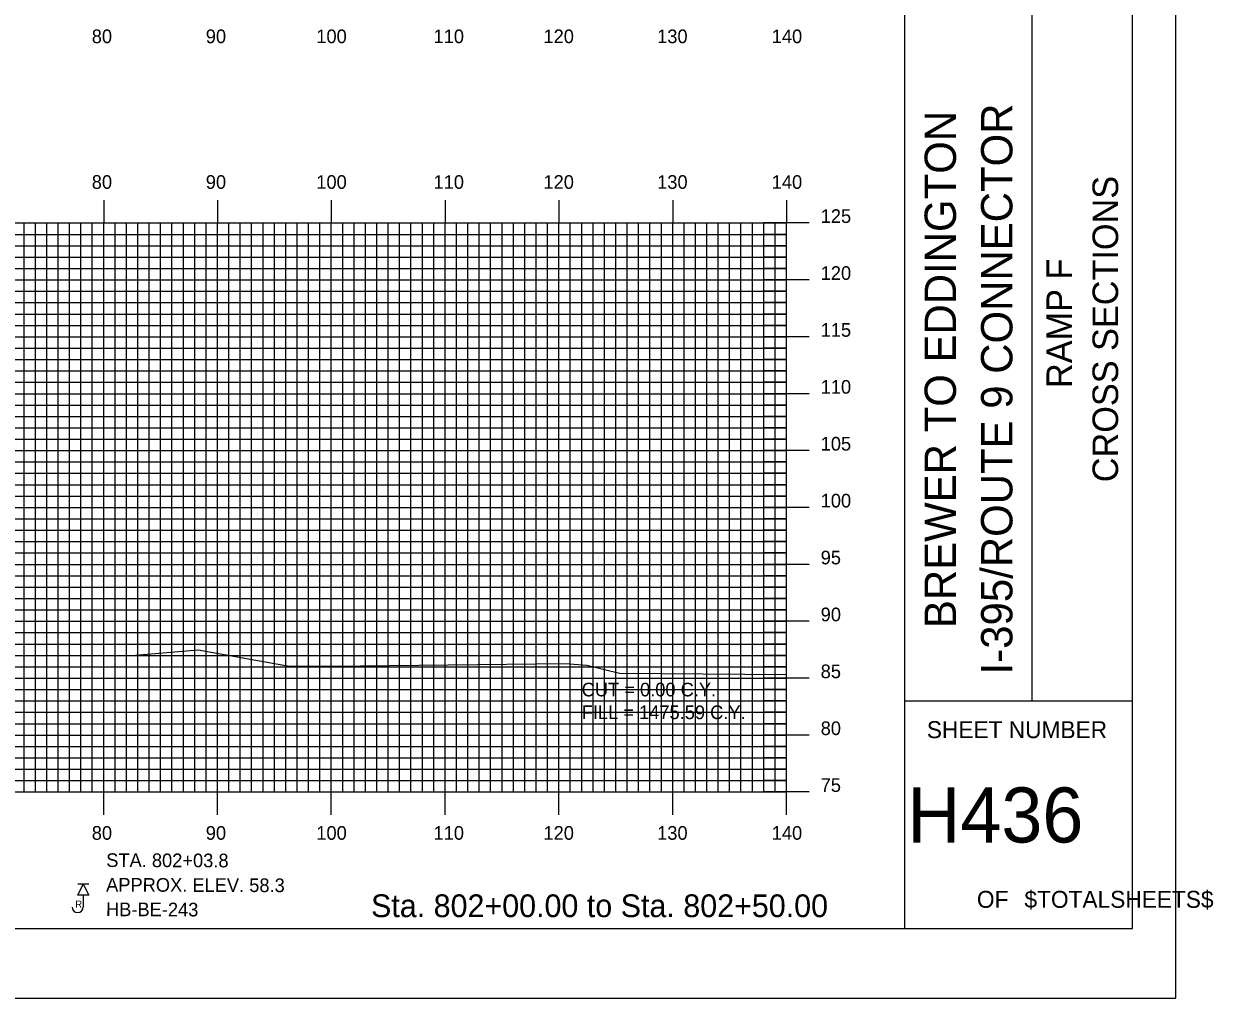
# Model space of a CAD drawing. Extents: x -302 to 42, y -1658 to -1438.
# Drawn here: x -62.9 to 41.6, y -1657.7 to -1572.1 of the extents above; entities that cross this region are included whole.
import ezdxf

# ---------------------------------------------------------------- set-up
doc = ezdxf.new("R2010")
doc.units = 0
for name, color, linetype in [('BORDER', 7, 'Continuous'), ('BORING - REFUSAL', 7, 'Continuous'), ('D_Text_Standard', 7, 'Continuous'), ('H_V ANNOTATION', 7, 'Continuous'), ('MAJOR', 7, 'Continuous'), ('MINOR', 7, 'Continuous'), ('PLOT BOUNDARY', 7, 'Continuous'), ('S_Roadway_Centerline', 7, 'Continuous')]:
    doc.layers.add(name, color=color, linetype=linetype)

msp = doc.modelspace()

# ---------------------------------------------------------------- linework, layer by layer
at = {"layer": 'BORDER'}
for p, q in [((14.51, -1651.6), (14.51, -1441.6)), ((25.69, -1631.6), (25.69, -1561.6)), ((14.51, -1631.6), (34.51, -1631.6))]:
    msp.add_line(p, q, dxfattribs=at)
msp.add_lwpolyline([(-285.49, -1651.6), (34.51, -1651.6), (34.51, -1441.6), (-285.49, -1441.6)], close=True, dxfattribs=at)
at = {"layer": 'BORING - REFUSAL'}
for p, q in [((-57.21, -1647.7), (-58.17, -1647.7)), ((-57.69, -1648.66), (-57.69, -1649.72))]:
    msp.add_line(p, q, dxfattribs=at)
msp.add_lwpolyline([(-57.69, -1647.7), (-57.21, -1648.66), (-58.17, -1648.66)], close=True, dxfattribs=at)
msp.add_arc((-58.18, -1649.72), 0.485, 180, 0, dxfattribs=at)
at = {"layer": 'MAJOR'}
for p, q in [((-55.89, -1587.6), (-55.89, -1589.6)), ((-45.89, -1587.6), (-45.89, -1589.6)), ((-35.89, -1587.6), (-35.89, -1589.6)), ((-25.89, -1587.6), (-25.89, -1589.6)), ((-15.89, -1587.6), (-15.89, -1589.6)), ((-5.89, -1587.6), (-5.89, -1589.6)), ((4.11, -1587.6), (4.11, -1589.6)), ((-275.89, -1589.6), (4.11, -1589.6)), ((-275.89, -1589.6), (4.11, -1589.6)), ((-55.89, -1639.6), (-55.89, -1589.6)), ((-45.89, -1639.6), (-45.89, -1589.6)), ((-35.89, -1639.6), (-35.89, -1589.6)), ((-25.89, -1639.6), (-25.89, -1589.6)), ((-15.89, -1639.6), (-15.89, -1589.6)), ((-5.89, -1639.6), (-5.89, -1589.6)), ((6.11, -1589.6), (2.1, -1589.6)), ((4.11, -1639.6), (4.11, -1589.6)), ((4.11, -1639.6), (4.11, -1589.6)), ((-275.89, -1594.6), (4.11, -1594.6)), ((6.11, -1594.6), (2.1, -1594.6)), ((-275.89, -1599.6), (4.11, -1599.6)), ((6.11, -1599.6), (2.1, -1599.6)), ((-275.89, -1604.6), (4.11, -1604.6)), ((6.11, -1604.6), (2.1, -1604.6)), ((-275.89, -1609.6), (4.11, -1609.6)), ((6.11, -1609.6), (2.1, -1609.6)), ((-275.89, -1614.6), (4.11, -1614.6)), ((6.11, -1614.6), (2.1, -1614.6)), ((-275.89, -1619.6), (4.11, -1619.6)), ((6.11, -1619.6), (2.1, -1619.6)), ((-275.89, -1624.6), (4.11, -1624.6)), ((6.11, -1624.6), (2.1, -1624.6)), ((-275.89, -1629.6), (4.11, -1629.6)), ((6.11, -1629.6), (2.1, -1629.6)), ((-275.89, -1634.6), (4.11, -1634.6)), ((6.11, -1634.6), (2.1, -1634.6)), ((-275.89, -1639.6), (4.11, -1639.6)), ((-275.89, -1639.6), (4.11, -1639.6)), ((-55.89, -1641.61), (-55.89, -1639.6)), ((-45.89, -1641.61), (-45.89, -1639.6)), ((-35.89, -1641.61), (-35.89, -1639.6)), ((-25.89, -1641.61), (-25.89, -1639.6)), ((-15.89, -1641.61), (-15.89, -1639.6)), ((-5.89, -1641.61), (-5.89, -1639.6)), ((6.11, -1639.6), (2.1, -1639.6)), ((4.11, -1641.61), (4.11, -1639.6))]:
    msp.add_line(p, q, dxfattribs=at)
at = {"layer": 'MINOR'}
for p, q in [((-62.89, -1639.6), (-62.89, -1589.6)), ((-61.89, -1639.6), (-61.89, -1589.6)), ((-60.89, -1639.6), (-60.89, -1589.6)), ((-59.89, -1639.6), (-59.89, -1589.6)), ((-58.89, -1639.6), (-58.89, -1589.6)), ((-57.89, -1639.6), (-57.89, -1589.6)), ((-56.89, -1639.6), (-56.89, -1589.6)), ((-54.89, -1639.6), (-54.89, -1589.6)), ((-53.89, -1639.6), (-53.89, -1589.6)), ((-52.89, -1639.6), (-52.89, -1589.6)), ((-51.89, -1639.6), (-51.89, -1589.6)), ((-50.89, -1639.6), (-50.89, -1589.6)), ((-49.89, -1639.6), (-49.89, -1589.6)), ((-48.89, -1639.6), (-48.89, -1589.6)), ((-47.89, -1639.6), (-47.89, -1589.6)), ((-46.89, -1639.6), (-46.89, -1589.6)), ((-44.89, -1639.6), (-44.89, -1589.6)), ((-43.89, -1639.6), (-43.89, -1589.6)), ((-42.89, -1639.6), (-42.89, -1589.6)), ((-41.89, -1639.6), (-41.89, -1589.6)), ((-40.89, -1639.6), (-40.89, -1589.6)), ((-39.89, -1639.6), (-39.89, -1589.6)), ((-38.89, -1639.6), (-38.89, -1589.6)), ((-37.89, -1639.6), (-37.89, -1589.6)), ((-36.89, -1639.6), (-36.89, -1589.6)), ((-34.89, -1639.6), (-34.89, -1589.6)), ((-33.89, -1639.6), (-33.89, -1589.6)), ((-32.89, -1639.6), (-32.89, -1589.6)), ((-31.89, -1639.6), (-31.89, -1589.6)), ((-30.89, -1639.6), (-30.89, -1589.6)), ((-29.89, -1639.6), (-29.89, -1589.6)), ((-28.89, -1639.6), (-28.89, -1589.6)), ((-27.89, -1639.6), (-27.89, -1589.6)), ((-26.89, -1639.6), (-26.89, -1589.6)), ((-24.89, -1639.6), (-24.89, -1589.6)), ((-23.89, -1639.6), (-23.89, -1589.6)), ((-22.89, -1639.6), (-22.89, -1589.6)), ((-21.89, -1639.6), (-21.89, -1589.6)), ((-20.89, -1639.6), (-20.89, -1589.6)), ((-19.89, -1639.6), (-19.89, -1589.6)), ((-18.89, -1639.6), (-18.89, -1589.6)), ((-17.89, -1639.6), (-17.89, -1589.6)), ((-16.89, -1639.6), (-16.89, -1589.6)), ((-14.89, -1639.6), (-14.89, -1589.6)), ((-13.89, -1639.6), (-13.89, -1589.6)), ((-12.89, -1639.6), (-12.89, -1589.6)), ((-11.89, -1639.6), (-11.89, -1589.6)), ((-10.89, -1639.6), (-10.89, -1589.6)), ((-9.89, -1639.6), (-9.89, -1589.6)), ((-8.89, -1639.6), (-8.89, -1589.6)), ((-7.89, -1639.6), (-7.89, -1589.6)), ((-6.89, -1639.6), (-6.89, -1589.6)), ((-4.89, -1639.6), (-4.89, -1589.6)), ((-3.89, -1639.6), (-3.89, -1589.6)), ((-2.89, -1639.6), (-2.89, -1589.6)), ((-1.89, -1639.6), (-1.89, -1589.6)), ((-0.89, -1639.6), (-0.89, -1589.6)), ((0.11, -1639.6), (0.11, -1589.6)), ((1.11, -1639.6), (1.11, -1589.6)), ((2.11, -1639.6), (2.11, -1589.6)), ((3.11, -1639.6), (3.11, -1589.6)), ((-275.89, -1590.6), (4.11, -1590.6)), ((4.11, -1590.6), (2.1, -1590.6)), ((-275.89, -1591.6), (4.11, -1591.6)), ((4.11, -1591.6), (2.1, -1591.6)), ((-275.89, -1592.6), (4.11, -1592.6)), ((4.11, -1592.6), (2.1, -1592.6)), ((-275.89, -1593.6), (4.11, -1593.6)), ((4.11, -1593.6), (2.1, -1593.6)), ((-275.89, -1595.6), (4.11, -1595.6)), ((4.11, -1595.6), (2.1, -1595.6)), ((-275.89, -1596.6), (4.11, -1596.6)), ((4.11, -1596.6), (2.1, -1596.6)), ((-275.89, -1597.6), (4.11, -1597.6)), ((4.11, -1597.6), (2.1, -1597.6)), ((-275.89, -1598.6), (4.11, -1598.6)), ((4.11, -1598.6), (2.1, -1598.6)), ((-275.89, -1600.6), (4.11, -1600.6)), ((4.11, -1600.6), (2.1, -1600.6)), ((-275.89, -1601.6), (4.11, -1601.6)), ((4.11, -1601.6), (2.1, -1601.6)), ((-275.89, -1602.6), (4.11, -1602.6)), ((4.11, -1602.6), (2.1, -1602.6)), ((-275.89, -1603.6), (4.11, -1603.6)), ((4.11, -1603.6), (2.1, -1603.6)), ((-275.89, -1605.6), (4.11, -1605.6)), ((4.11, -1605.6), (2.1, -1605.6)), ((-275.89, -1606.6), (4.11, -1606.6)), ((4.11, -1606.6), (2.1, -1606.6)), ((-275.89, -1607.6), (4.11, -1607.6)), ((4.11, -1607.6), (2.1, -1607.6)), ((-275.89, -1608.6), (4.11, -1608.6)), ((4.11, -1608.6), (2.1, -1608.6)), ((-275.89, -1610.6), (4.11, -1610.6)), ((4.11, -1610.6), (2.1, -1610.6)), ((-275.89, -1611.6), (4.11, -1611.6)), ((4.11, -1611.6), (2.1, -1611.6)), ((-275.89, -1612.6), (4.11, -1612.6)), ((4.11, -1612.6), (2.1, -1612.6)), ((-275.89, -1613.6), (4.11, -1613.6)), ((4.11, -1613.6), (2.1, -1613.6)), ((-275.89, -1615.6), (4.11, -1615.6)), ((4.11, -1615.6), (2.1, -1615.6)), ((-275.89, -1616.6), (4.11, -1616.6)), ((4.11, -1616.6), (2.1, -1616.6)), ((-275.89, -1617.6), (4.11, -1617.6)), ((4.11, -1617.6), (2.1, -1617.6)), ((-275.89, -1618.6), (4.11, -1618.6)), ((4.11, -1618.6), (2.1, -1618.6)), ((-275.89, -1620.6), (4.11, -1620.6)), ((4.11, -1620.6), (2.1, -1620.6)), ((-275.89, -1621.6), (4.11, -1621.6)), ((4.11, -1621.6), (2.1, -1621.6)), ((-275.89, -1622.6), (4.11, -1622.6)), ((4.11, -1622.6), (2.1, -1622.6)), ((-275.89, -1623.6), (4.11, -1623.6)), ((4.11, -1623.6), (2.1, -1623.6)), ((-275.89, -1625.6), (4.11, -1625.6)), ((4.11, -1625.6), (2.1, -1625.6)), ((-275.89, -1626.6), (4.11, -1626.6)), ((4.11, -1626.6), (2.1, -1626.6)), ((-275.89, -1627.6), (4.11, -1627.6)), ((4.11, -1627.6), (2.1, -1627.6)), ((-275.89, -1628.6), (4.11, -1628.6)), ((4.11, -1628.6), (2.1, -1628.6)), ((-275.89, -1630.6), (4.11, -1630.6)), ((4.11, -1630.6), (2.1, -1630.6)), ((-275.89, -1631.6), (4.11, -1631.6)), ((4.11, -1631.6), (2.1, -1631.6)), ((-275.89, -1632.6), (4.11, -1632.6)), ((4.11, -1632.6), (2.1, -1632.6)), ((-275.89, -1633.6), (4.11, -1633.6)), ((4.11, -1633.6), (2.1, -1633.6)), ((-275.89, -1635.6), (4.11, -1635.6)), ((4.11, -1635.6), (2.1, -1635.6)), ((-275.89, -1636.6), (4.11, -1636.6)), ((4.11, -1636.6), (2.1, -1636.6)), ((-275.89, -1637.6), (4.11, -1637.6)), ((4.11, -1637.6), (2.1, -1637.6)), ((-275.89, -1638.6), (4.11, -1638.6)), ((4.11, -1638.6), (2.1, -1638.6))]:
    msp.add_line(p, q, dxfattribs=at)
at = {"layer": 'PLOT BOUNDARY'}
msp.add_lwpolyline([(-301.68, -1657.72), (38.32, -1657.72), (38.32, -1437.72), (-301.68, -1437.72)], close=True, dxfattribs=at)
at = {"layer": 'S_Roadway_Centerline'}
msp.add_lwpolyline([(-64, -1627.57), (-53.46, -1627.62), (-47.6, -1627.11), (-39.73, -1628.52), (-35.91, -1628.55), (-15.34, -1628.32), (-13.44, -1628.46), (-10.58, -1629.16), (4.11, -1629.29)], dxfattribs=at)

# ---------------------------------------------------------------- texts
at = {"layer": 'BORDER'}
for s, height, p in [('BREWER TO EDDINGTON', 2.7557, (19, -1625.2)), ('I-395/ROUTE 9 CONNECTOR', 2.7557, (23.96, -1629.27)), ('CROSS SECTIONS', 2.25, (33.25, -1612.38)), ('RAMP F', 2.25, (29.2, -1604.1))]:
    msp.add_text(s, height=height, rotation=90, dxfattribs=at).set_placement(p)
for s, height, p in [('SHEET NUMBER', 1.4905, (16.44, -1634.87)), ('H436', 4.839, (14.72, -1644.04)), ('$TOTALSHEETS$', 1.4905, (25.02, -1649.78)), ('OF', 1.491, (20.84, -1649.78))]:
    msp.add_text(s, height=height, dxfattribs=at).set_placement(p)
at = {"layer": 'BORING - REFUSAL'}
for s, p in [('STA. 802+03.8', (-55.67, -1646.19)), ('APPROX. ELEV. 58.3', (-55.68, -1648.35)), ('HB-BE-243', (-55.69, -1650.51))]:
    msp.add_text(s, height=1.2, rotation=359.8142, dxfattribs=at).set_placement(p)
msp.add_text('R', height=0.64, dxfattribs=at).set_placement((-58.4, -1649.78))
at = {"layer": 'D_Text_Standard'}
for s, p in [('CUT = 0.00 C.Y.', (-13.89, -1631.2)), ('FILL = 1475.59 C.Y.', (-13.89, -1633.2))]:
    msp.add_text(s, height=1.2, dxfattribs=at).set_placement(p)
at = {"layer": 'H_V ANNOTATION'}
for s, height, p in [('80', 1.2, (-56.94, -1573.8)), ('90', 1.2, (-46.92, -1573.8)), ('100', 1.2, (-37.21, -1573.8)), ('110', 1.2, (-26.91, -1573.8)), ('120', 1.2, (-17.25, -1573.8)), ('130', 1.2, (-7.26, -1573.8)), ('140', 1.2, (2.81, -1573.8)), ('80', 1.2, (-56.94, -1586.6)), ('90', 1.2, (-46.92, -1586.6)), ('100', 1.2, (-37.21, -1586.6)), ('110', 1.2, (-26.91, -1586.6)), ('120', 1.2, (-17.25, -1586.6)), ('130', 1.2, (-7.26, -1586.6)), ('140', 1.2, (2.81, -1586.6)), ('125', 1.2, (7.11, -1589.6)), ('120', 1.2, (7.11, -1594.6)), ('115', 1.2, (7.11, -1599.6)), ('110', 1.2, (7.11, -1604.6)), ('105', 1.2, (7.11, -1609.6)), ('100', 1.2, (7.11, -1614.6)), ('95', 1.2, (7.11, -1619.6)), ('90', 1.2, (7.11, -1624.6)), ('85', 1.2, (7.11, -1629.6)), ('80', 1.2, (7.11, -1634.6)), ('75', 1.2, (7.11, -1639.6)), ('80', 1.2, (-56.94, -1643.8)), ('90', 1.2, (-46.92, -1643.8)), ('100', 1.2, (-37.21, -1643.8)), ('110', 1.2, (-26.91, -1643.8)), ('120', 1.2, (-17.25, -1643.8)), ('130', 1.2, (-7.26, -1643.8)), ('140', 1.2, (2.81, -1643.8)), ('Sta. 802+00.00 to Sta. 802+50.00', 2.0004, (-32.4, -1650.6))]:
    msp.add_text(s, height=height, dxfattribs=at).set_placement(p)

doc.saveas('drawing.dxf')
